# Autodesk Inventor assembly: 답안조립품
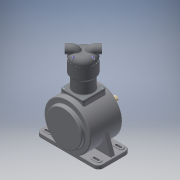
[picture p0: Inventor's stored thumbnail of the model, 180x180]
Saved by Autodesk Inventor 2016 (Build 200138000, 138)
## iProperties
Created: 2015-06
Part Number: 답안조립품
Document SubType Name: Assembly
Designer: Administrator
Author: Administrator
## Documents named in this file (14)
- C:\Users\Administrator\Desktop\450606V1033\답안조립품.iam
- C:\Users\Administrator\Desktop\450606V1033\본체.ipt
- C:\Users\Administrator\Desktop\450606V1033\크랭크 서브축.ipt
- C:\Users\Administrator\Desktop\450606V1033\메인 크랭크 축-구동부.ipt
- C:\Users\Administrator\Desktop\450606V1033\커넥팅 로드.ipt
- C:\Users\Administrator\Desktop\450606V1033\베어링 NA 4902.ipt
- C:\Users\Administrator\Desktop\450606V1033\베어링 6204.ipt
- C:\Users\Administrator\Desktop\450606V1033\메인커버.ipt
- C:\Users\Administrator\Desktop\450606V1033\오일실.ipt
- C:\Users\Administrator\Desktop\450606V1033\실린더.ipt
- C:\Users\Administrator\Desktop\450606V1033\피스톤.ipt
- C:\Users\Administrator\Desktop\450606V1033\피스톤 핀.ipt
- C:\Users\Administrator\Desktop\450606V1033\실린더헤드.ipt
- C:\Users\Administrator\Desktop\450606V1033\M5x0.8.ipt
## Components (6 placed, 3 different names)
1. 피스톤:1
2. 피스톤 핀:1
3. M5x0.8:1
4. M5x0.8:2
5. M5x0.8:3
6. M5x0.8:4
